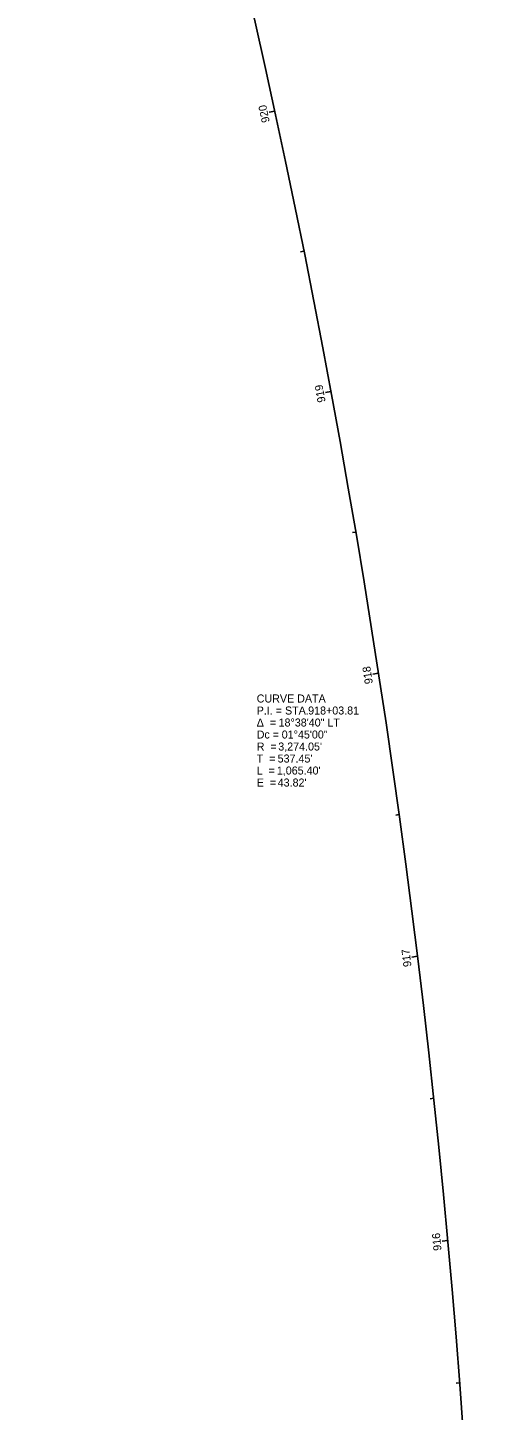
# Model space of a CAD drawing. Extents: x 145633 to 146120, y 414528 to 417535.
# Drawn here: x 145927.2 to 146087.6, y 416069.5 to 416553.3 of the extents above; entities that cross this region are included whole.
import ezdxf

# ---------------------------------------------------------------- set-up
doc = ezdxf.new("R2010")
doc.units = 0
for name, color, linetype in [('GE_X_Alignment', 7, 'Continuous'), ('GE_X_Alignment_100_Curve_Data', 7, 'Continuous'), ('GE_X_Alignment_100_Stations', 7, 'Continuous'), ('SC_Scratch3', 7, 'Continuous')]:
    doc.layers.add(name, color=color, linetype=linetype)

msp = doc.modelspace()

# ---------------------------------------------------------------- linework, layer by layer
at = {"layer": 'GE_X_Alignment'}
msp.add_arc((142813.52, 415832.16), 3274.05, 359.36198, 18.00643, dxfattribs=at)
at = {"layer": 'GE_X_Alignment_100_Stations'}
for p, q in [((146013.62, 416524.08), (146011.67, 416523.66)), ((146023.82, 416475.13), (146022.64, 416474.9)), ((146033.26, 416426.03), (146031.29, 416425.67)), ((146041.95, 416376.8), (146040.77, 416376.6)), ((146049.89, 416327.43), (146047.92, 416327.13)), ((146057.08, 416277.95), (146055.89, 416277.79)), ((146063.51, 416228.37), (146061.52, 416228.12)), ((146069.18, 416178.69), (146067.99, 416178.56)), ((146074.09, 416128.93), (146072.1, 416128.75)), ((146078.25, 416079.1), (146077.05, 416079.01))]:
    msp.add_line(p, q, dxfattribs=at)
at = {"layer": 'SC_Scratch3'}
msp.add_arc((142813.52, 415832.16), 3274.05, 359.36198, 18.00643, dxfattribs=at)

# ---------------------------------------------------------------- texts
at = {"layer": 'GE_X_Alignment_100_Curve_Data'}
for s, p in [('CURVE DATA', (146007.29, 416317.17)), ('P.I. = STA. ', (146007.29, 416312.97)), ('918+03.81', (146025.28, 416312.97)), ('Δ  = ', (146007.29, 416308.77)), ('18°38\'40" LT', (146014.94, 416308.77)), ('Dc = ', (146007.29, 416304.57)), ('01°45\'00"', (146016.04, 416304.57)), ('R  = ', (146007.29, 416300.37)), ("3,274.05'", (146014.83, 416300.37)), ('T  = ', (146007.29, 416296.17)), ("537.45'", (146014.61, 416296.17)), ('L  = ', (146007.29, 416291.97)), ('E  = ', (146007.29, 416287.77)), ("1,065.40'", (146014.33, 416291.97)), ("43.82'", (146014.63, 416287.77))]:
    msp.add_text(s, height=2.8, dxfattribs=at).set_placement(p)
at = {"layer": 'GE_X_Alignment_100_Stations'}
for s, rotation, p in [('920', 102.2007, (146011.87, 416520.36)), ('919', 100.4507, (146031.39, 416422.41)), ('918', 98.7007, (146047.91, 416323.84)), ('917', 96.9507, (146061.42, 416224.84)), ('916', 95.2007, (146071.9, 416125.46))]:
    msp.add_text(s, height=2.8, rotation=rotation, dxfattribs=at).set_placement(p)

doc.saveas('drawing.dxf')
